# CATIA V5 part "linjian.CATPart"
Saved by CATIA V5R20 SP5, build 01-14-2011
Part number: 3.29
Bounding box of the stored display mesh (mm): x -100 to 100, y -99.999 to 99.999, z -2.5 to 22.456
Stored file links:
  E:\180132104于洋\Part3.CATPart
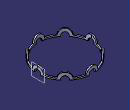
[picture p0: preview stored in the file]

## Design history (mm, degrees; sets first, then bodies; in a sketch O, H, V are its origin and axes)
Body1 (main body)
  Sketch1 on xy-plane, origin (0, 0, 0), H (1, 0, 0), V (0, 1, 0)
    circle A1 centre (0, 0) radius 100
    radius A1 = 100
  Pad1: profile Sketch1, direction (0, 0, 1), length 2.5, mirrored extent, thin wall 5
  Body2
    Sketch2 on xy-plane, origin (0, 0, 0), H (1, 0, 0), V (0, 1, 0)
      arc A1 centre (100, 0) radius 20 from (97.5, -19.8431) to (97.5, 19.8431) ccw
      point P1 (100, 0)
      axis line L1 (97.5, 70) -> (97.5, -80)
      point P2 (97.5, 70)
      point P4 (97.5, 19.8431)
      point P5 (97.5, -19.8431)
      radius A1 = 20
      distance P2 V = 97.5
      coincidence: P1 H, L1 P4, L1 P5
      vertical: L1 V
    Shaft1: profile Sketch2, axis Sketch2.L1, angle 360
    CircPattern1: of Shaft1, instances 8, angular step 45, axis from end face of Pad1
    Sketch3 on xy-plane, origin (0, 0, 0), H (1, 0, 0), V (0, 1, 0)
      circle A1 centre (0, 0) radius 95
      radius A1 = 95
    Pocket1: profile Sketch3, direction (0, 0, -1), length 30, mirrored extent
    Split1: SplitPlane start face of Pad1
    Sketch4 on xy-plane, origin (0, 0, 0), H (1, 0, 0), V (0, 1, 0)
      circle A1 centre (0, 0) radius 100
      radius A1 = 100
    Pocket2: profile Sketch4, direction (0, 0, -1), length 30, mirrored extent, outer side
  Assemble1: tool Body2
  Body3
    Plane1: type Offset, RefPlane yz-plane, Offset 97.5
    Sketch5 on Plane1, origin (97.5, 0, 0), H (0, 1, 0), V (0, 0, 1)
      arc A1 centre (0, 0) radius 12 from (-12, 0) to (12, 0) ccw
      axis line L1 (-20, 0) -> (20, 0)
      point P1 (-20, 0)
      point P3 (-12, 0)
      point P4 (12, 0)
      radius A1 = 12
      coincidence: P1 H, L1 P4, L1 P3
      horizontal: L1 H
    Shaft2: profile Sketch5, axis Sketch5.L1, angle 360
    CircPattern2: of the body so far, instances 8, angular step 45, axis from end face of Pad1
  Remove1: tool Body3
